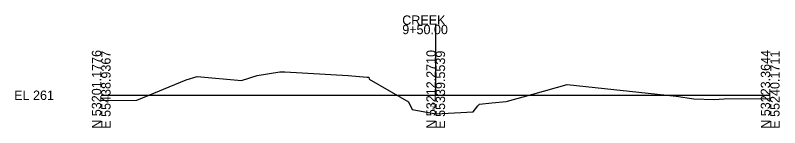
# Model space of a CAD drawing. Extents: x 7498 to 7727, y 91719 to 100242.
# Drawn here: x 7498.3 to 7726.8, y 95219.2 to 95252.7 of the extents above; entities that cross this region are included whole.
import ezdxf

# ---------------------------------------------------------------- set-up
doc = ezdxf.new("R2010")
doc.units = 0
for name, color, linetype in [('Level 10', 7, 'Continuous'), ('Level 60', 7, 'Continuous'), ('Level 63', 7, 'Continuous')]:
    doc.layers.add(name, color=color, linetype=linetype)

msp = doc.modelspace()

# ---------------------------------------------------------------- linework, layer by layer
at = {"layer": 'Level 60'}
for p, q in [((7549.37, 95233.46), (7552.69, 95234.5)), ((7552.69, 95234.5), (7565.92, 95233.21)), ((7565.92, 95233.21), (7570.64, 95234.77)), ((7570.64, 95234.77), (7577.38, 95235.84)), ((7577.38, 95235.84), (7578.92, 95235.87)), ((7578.92, 95235.87), (7597.81, 95234.76)), ((7597.81, 95234.76), (7603.49, 95234.26)), ((7603.49, 95234.26), (7603.97, 95234.26)), ((7603.97, 95234.26), (7604.11, 95233.67)), ((7534.63, 95227.35), (7549.37, 95233.46)), ((7604.11, 95233.67), (7615.89, 95226.89)), ((7653, 95229.19), (7663.32, 95232.07)), ((7663.32, 95232.07), (7695.92, 95228.56)), ((7645.47, 95227.09), (7653, 95229.19)), ((7695.92, 95228.56), (7701.13, 95227.8)), ((7701.13, 95227.8), (7707.21, 95227.56)), ((7707.21, 95227.56), (7710.18, 95227.74)), ((7710.18, 95227.74), (7723.99, 95227.9)), ((7523.99, 95227.24), (7534.63, 95227.35)), ((7615.89, 95226.89), (7616.91, 95224.57)), ((7635.2, 95223.91), (7636.54, 95225.65)), ((7636.54, 95225.65), (7637.11, 95226.18)), ((7637.11, 95226.18), (7640.81, 95226.58)), ((7640.81, 95226.58), (7645.06, 95226.96)), ((7645.06, 95226.96), (7645.47, 95227.09)), ((7616.91, 95224.57), (7623.99, 95223.32)), ((7623.99, 95223.32), (7635.2, 95223.91))]:
    msp.add_line(p, q, dxfattribs=at)
at = {"layer": 'Level 63'}
for p, q in [((7623.99, 95228.85), (7623.99, 95249.89)), ((7523.99, 95228.85), (7623.99, 95228.85)), ((7623.99, 95228.85), (7723.99, 95228.85))]:
    msp.add_line(p, q, dxfattribs=at)

# ---------------------------------------------------------------- texts
at = {"layer": 'Level 10'}
msp.add_text('255.47', height=0.6, rotation=90, dxfattribs=at).set_placement((7623.59, 95224.32))
at = {"layer": 'Level 63'}
for s, p in [('CREEK', (7613.99, 95249.89)), ('9+50.00', (7613.99, 95247.09)), ('EL 261', (7497.99, 95227.45))]:
    msp.add_text(s, height=2.8, dxfattribs=at).set_placement(p)
for s, p in [('N 53201.1776', (7523.99, 95218.85)), ('E 55438.9367', (7526.79, 95218.85)), ('N 53212.2710', (7623.99, 95218.85)), ('E 55339.5539', (7626.79, 95218.85)), ('N 53223.3644', (7723.99, 95218.85)), ('E 55240.1711', (7726.79, 95218.85))]:
    msp.add_text(s, height=2.8, rotation=90, dxfattribs=at).set_placement(p)

doc.saveas('drawing.dxf')
